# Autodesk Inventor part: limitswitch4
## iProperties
Created: 2002-01
Part Number: limitswitch4
Document SubType Name: Modeling
Density: 1 g/cm^3
Control State: 0
Master: False
Checked Out: False
Shininess: 0.0
Density: 0.0
Volumn: 0.0
Area: 0.0
PropertySet Name: Model Information
Author: Administrator
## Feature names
1. Chamfer1
2. Extrusion1
